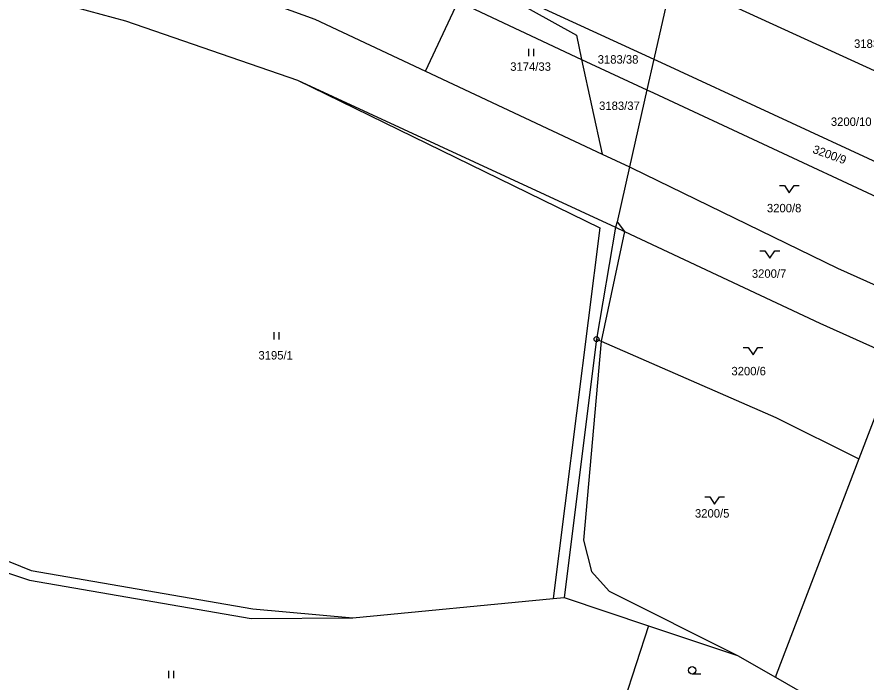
# Model space of a CAD drawing. Extents: x -593183 to -588034, y -1130415 to -1124994.
# Drawn here: x -592501.6 to -592330.3, y -1127837.6 to -1127703.4 of the extents above; entities that cross this region are included whole.
import ezdxf

# ---------------------------------------------------------------- set-up
doc = ezdxf.new("R2010")
doc.units = 0
for name, color, linetype in [('Vrstva 1', 7, 'Continuous'), ('Vrstva 18', 7, 'Continuous'), ('Vrstva 24', 7, 'Continuous'), ('Vrstva 25', 7, 'Continuous'), ('Vrstva 4', 7, 'Continuous')]:
    doc.layers.add(name, color=color, linetype=linetype)

msp = doc.modelspace()

# ---------------------------------------------------------------- linework, layer by layer
at = {"layer": 'Vrstva 1'}
for p, q in [((-592477.35, -1127690.81), (-592441.52, -1127703.8)), ((-592513.41, -1127695.01), (-592479.67, -1127704.15)), ((-592369.42, -1127695.5), (-592373.11, -1127711.87)), ((-592369.42, -1127695.5), (-592319.21, -1127718.51)), ((-592404.22, -1127698.44), (-592388.73, -1127707.07)), ((-592404.14, -1127697.63), (-592373.11, -1127711.87)), ((-592419.14, -1127714.32), (-592412.58, -1127700.3)), ((-592412.58, -1127700.3), (-592387.67, -1127711.95)), ((-592479.67, -1127704.15), (-592445, -1127716.12)), ((-592441.52, -1127703.8), (-592419.14, -1127714.32)), ((-592388.73, -1127707.07), (-592387.67, -1127711.95)), ((-592387.67, -1127711.95), (-592374.52, -1127718.1)), ((-592387.67, -1127711.95), (-592383.51, -1127731.06)), ((-592373.11, -1127711.87), (-592374.52, -1127718.1)), ((-592373.11, -1127711.87), (-592371.6, -1127712.58)), ((-592371.6, -1127712.58), (-592325.84, -1127733.78)), ((-592419.14, -1127714.32), (-592383.51, -1127731.06)), ((-592445, -1127716.12), (-592380.81, -1127745.82)), ((-592374.52, -1127718.1), (-592378.02, -1127733.64)), ((-592374.52, -1127718.1), (-592373.2, -1127718.72)), ((-592373.2, -1127718.72), (-592327.02, -1127740.24)), ((-592383.51, -1127731.06), (-592378.02, -1127733.64)), ((-592378.02, -1127733.64), (-592380.53, -1127744.76)), ((-592378.02, -1127733.64), (-592377.63, -1127733.82)), ((-592377.63, -1127733.82), (-592336.06, -1127754.07)), ((-592380.53, -1127744.76), (-592380.81, -1127745.82)), ((-592380.81, -1127745.82), (-592384.66, -1127768.39)), ((-592380.81, -1127745.82), (-592379, -1127746.67)), ((-592379, -1127746.67), (-592339.64, -1127765.19)), ((-592336.06, -1127754.07), (-592319.85, -1127761.37)), ((-592339.64, -1127765.19), (-592324, -1127772.24)), ((-592384.66, -1127768.39), (-592391.2, -1127820.53)), ((-592384.66, -1127768.39), (-592383.74, -1127768.79)), ((-592383.74, -1127768.79), (-592348.52, -1127784.24)), ((-592324, -1127772.24), (-592331.75, -1127792.55)), ((-592348.52, -1127784.24), (-592331.75, -1127792.55)), ((-592331.75, -1127792.55), (-592348.4, -1127836.17)), ((-592510.29, -1127810.45), (-592498.7, -1127815.08)), ((-592498.7, -1127815.08), (-592454, -1127822.79)), ((-592393.39, -1127820.74), (-592391.2, -1127820.53)), ((-592391.2, -1127820.53), (-592374.16, -1127826.25)), ((-592433.8, -1127824.64), (-592393.39, -1127820.74)), ((-592454, -1127822.79), (-592433.8, -1127824.64)), ((-592374.16, -1127826.25), (-592379.36, -1127842.19)), ((-592374.16, -1127826.25), (-592356.22, -1127832.26)), ((-592356.22, -1127832.26), (-592348.57, -1127836.62)), ((-592348.4, -1127836.17), (-592348.57, -1127836.62)), ((-592348.57, -1127836.62), (-592340.15, -1127841.43))]:
    msp.add_line(p, q, dxfattribs=at)
at = {"layer": 'Vrstva 24'}
for radius in [0.5, 0.0327]:
    msp.add_circle((-592384.66, -1127768.39), radius, dxfattribs=at)
at = {"layer": 'Vrstva 25'}
for p, q in [((-592398.37, -1127709.81), (-592398.37, -1127711.31)), ((-592397.34, -1127711.31), (-592397.34, -1127709.81)), ((-592449.74, -1127767), (-592449.74, -1127768.5)), ((-592448.72, -1127768.5), (-592448.72, -1127767)), ((-592470.99, -1127835.32), (-592470.99, -1127836.82)), ((-592469.97, -1127836.82), (-592469.97, -1127835.32)), ((-592363.62, -1127835.98), (-592365.37, -1127835.98))]:
    msp.add_line(p, q, dxfattribs=at)
for points in [[(-592347.77, -1127737.4), (-592346.77, -1127737.4), (-592345.77, -1127738.9), (-592344.77, -1127737.4), (-592343.77, -1127737.4)], [(-592351.69, -1127750.56), (-592350.69, -1127750.56), (-592349.69, -1127752.06), (-592348.69, -1127750.56), (-592347.69, -1127750.56)], [(-592355.09, -1127770.08), (-592354.09, -1127770.08), (-592353.09, -1127771.58), (-592352.09, -1127770.08), (-592351.09, -1127770.08)], [(-592362.84, -1127800.21), (-592361.84, -1127800.21), (-592360.84, -1127801.71), (-592359.84, -1127800.21), (-592358.84, -1127800.21)]]:
    msp.add_lwpolyline(points, dxfattribs=at)
msp.add_circle((-592365.37, -1127835.23), 0.75, dxfattribs=at)
at = {"layer": 'Vrstva 4'}
for p, q in [((-592445, -1127716.12), (-592383.98, -1127745.92)), ((-592380.53, -1127744.76), (-592379, -1127746.67)), ((-592383.98, -1127745.92), (-592393.39, -1127820.74)), ((-592379, -1127746.67), (-592383.74, -1127768.79)), ((-592383.74, -1127768.79), (-592387.32, -1127808.95)), ((-592387.32, -1127808.95), (-592385.67, -1127815.29)), ((-592510.89, -1127813.08), (-592499.04, -1127817.05)), ((-592385.67, -1127815.29), (-592382.15, -1127819.24)), ((-592499.04, -1127817.05), (-592454.34, -1127824.76)), ((-592382.15, -1127819.24), (-592356.22, -1127832.26)), ((-592454.34, -1127824.76), (-592433.8, -1127824.64))]:
    msp.add_line(p, q, dxfattribs=at)

# ---------------------------------------------------------------- texts
at = {"layer": 'Vrstva 18'}
for s, p in [('3183/40', (-592332.71, -1127709.62)), ('3183/38', (-592384.43, -1127712.8)), ('3174/33', (-592402.08, -1127714.25)), ('3183/37', (-592384.15, -1127722.16)), ('3200/10', (-592337.39, -1127725.37)), ('3200/8', (-592350.29, -1127742.81)), ('3200/7', (-592353.33, -1127756.02)), ('3195/1', (-592452.88, -1127772.51)), ('3200/6', (-592357.45, -1127775.7)), ('3200/5', (-592364.81, -1127804.41))]:
    msp.add_text(s, height=1.7, dxfattribs=at).set_placement(p)
msp.add_text('3200/9', height=1.7, rotation=340.1614, dxfattribs=at).set_placement((-592341.2, -1127730.78))

doc.saveas('drawing.dxf')
